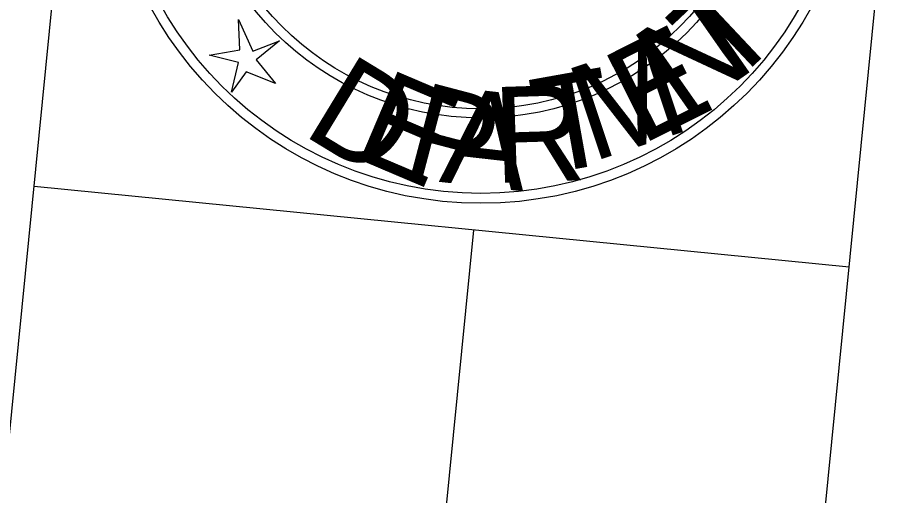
# Model space of a CAD drawing. Extents: x 1797076 to 1798338, y 246730 to 248530.
# Drawn here: x 1798184.1 to 1798236.9, y 247617.5 to 247646.7 of the extents above; entities that cross this region are included whole.
import ezdxf

# ---------------------------------------------------------------- set-up
doc = ezdxf.new("R2010")
doc.units = 0
for name, color, linetype in [('great seal', 7, 'Continuous'), ('SHT-BDR', 7, 'Continuous'), ('SHT-BNDRY', 7, 'Continuous')]:
    doc.layers.add(name, color=color, linetype=linetype)

msp = doc.modelspace()

# ---------------------------------------------------------------- linework, layer by layer
at = {"layer": 'great seal'}
msp.add_lwpolyline([(1798195.775, 247644.406), (1798197.657, 247644.747), (1798197.577, 247646.604), (1798198.442, 247644.67), (1798200.088, 247645.299), (1798198.651, 247644.121), (1798199.829, 247642.684), (1798198.051, 247643.388), (1798197.137, 247642.158), (1798197.58, 247643.963)], close=True, dxfattribs=at)
msp.add_lwpolyline([(1798195.775, 247644.406), (1798197.657, 247644.747), (1798197.577, 247646.604), (1798198.442, 247644.67), (1798200.088, 247645.299), (1798198.651, 247644.121), (1798199.829, 247642.684), (1798198.051, 247643.388), (1798197.137, 247642.158), (1798197.58, 247643.963)], close=True, dxfattribs=at)
msp.add_lwpolyline([(1798195.775, 247644.406), (1798197.657, 247644.747), (1798197.577, 247646.604), (1798198.442, 247644.67), (1798200.088, 247645.299), (1798198.651, 247644.121), (1798199.829, 247642.684), (1798198.051, 247643.388), (1798197.137, 247642.158), (1798197.58, 247643.963)], close=True, dxfattribs=at)
for radius in [22.994, 22.994, 22.994, 22.389, 22.389, 22.389, 17.779, 17.779, 17.779, 17.222, 17.222, 17.222]:
    msp.add_circle((1798212.392, 247658.358), radius, dxfattribs=at)
at = {"layer": 'SHT-BDR'}
msp.add_lwpolyline([(1798108.469, 246862.035), (1798256.169, 248354.749), (1797310.784, 248448.292), (1797163.084, 246955.579)], close=True, dxfattribs=at)
at = {"layer": 'SHT-BNDRY'}
for p, q in [((1798234.897, 247631.464), (1798185.09, 247636.393)), ((1798135.338, 246859.377), (1798211.959, 247633.734))]:
    msp.add_line(p, q, dxfattribs=at)
msp.add_lwpolyline([(1798152.124, 246794.926), (1798310.901, 248399.593), (1797266.002, 248502.983), (1797107.224, 246898.316)], close=True, dxfattribs=at)

# ---------------------------------------------------------------- texts
at = {"layer": 'great seal'}
for s, rotation, p in [('T', 43.2798, (1798227.519, 247642.321)), ('T', 43.2798, (1798227.519, 247642.321)), ('T', 43.2798, (1798227.519, 247642.321)), ('N', 34.9914, (1798224.697, 247640.488)), ('N', 34.9914, (1798224.697, 247640.488)), ('N', 34.9914, (1798224.697, 247640.488)), ('E', 26.703, (1798222.162, 247638.89)), ('E', 26.703, (1798222.162, 247638.89)), ('E', 26.703, (1798222.162, 247638.89)), ('M', 18.4147, (1798219.156, 247637.867)), ('M', 18.4147, (1798219.156, 247637.867)), ('M', 18.4147, (1798219.156, 247637.867)), ('D', 328.6843, (1798201.375, 247639.627)), ('D', 328.6843, (1798201.375, 247639.627)), ('D', 328.6843, (1798201.375, 247639.627)), ('E', 336.9727, (1798204.41, 247638.27)), ('E', 336.9727, (1798204.41, 247638.27)), ('E', 336.9727, (1798204.41, 247638.27)), ('T', 10.1263, (1798216.177, 247637.106)), ('T', 10.1263, (1798216.177, 247637.106)), ('T', 10.1263, (1798216.177, 247637.106)), ('P', 345.2611, (1798207.47, 247637.175)), ('P', 345.2611, (1798207.47, 247637.175)), ('P', 345.2611, (1798207.47, 247637.175)), ('A', 353.5495, (1798209.797, 247636.681)), ('A', 353.5495, (1798209.797, 247636.681)), ('A', 353.5495, (1798209.797, 247636.681)), ('R', 1.8379, (1798213.223, 247636.606)), ('R', 1.8379, (1798213.223, 247636.606)), ('R', 1.8379, (1798213.223, 247636.606))]:
    msp.add_text(s, height=5.851, rotation=rotation, dxfattribs=at).set_placement(p)

doc.saveas('drawing.dxf')
